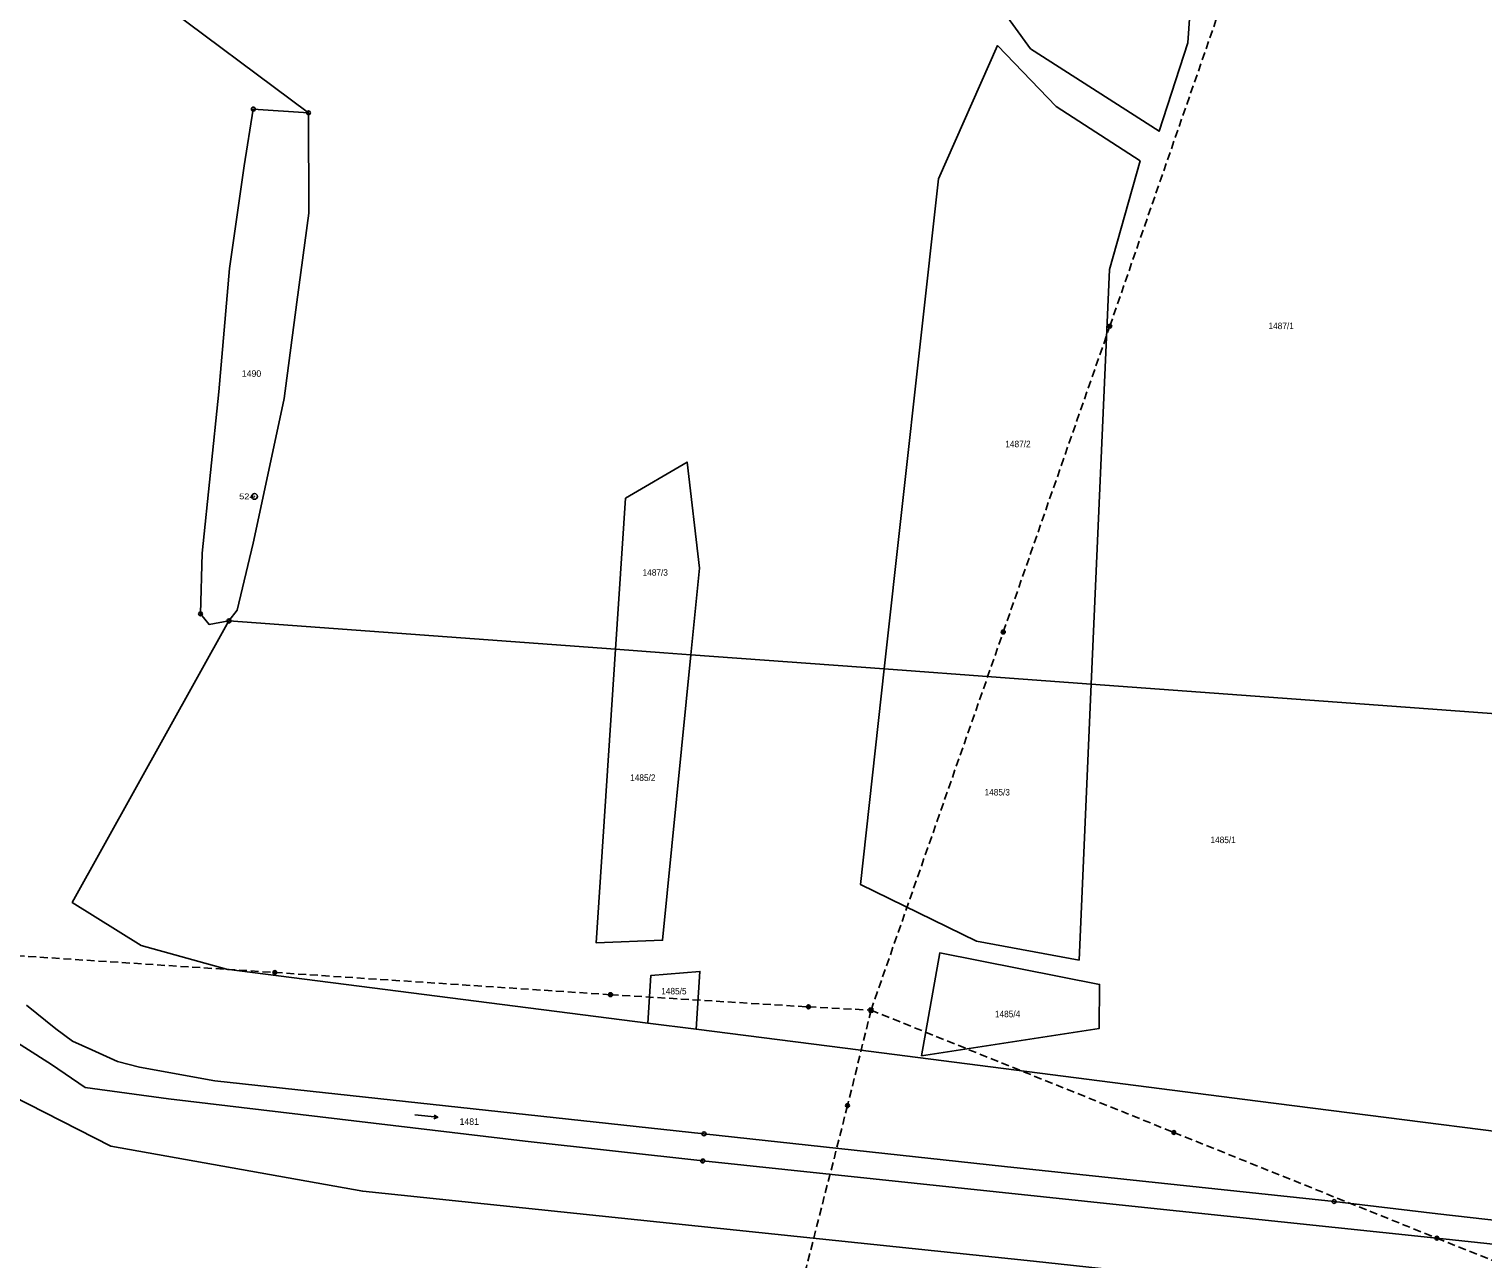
# Model space of a CAD drawing. Extents: x -872229 to -869198, y -1075981 to -1074329.
# Drawn here: x -871585.9 to -871207, y -1075209.5 to -1074889 of the extents above; entities that cross this region are included whole.
import ezdxf
from ezdxf.enums import TextEntityAlignment as Align

# ---------------------------------------------------------------- set-up
doc = ezdxf.new("R2010")
doc.units = 0
doc.header["$LTSCALE"] = 0.68
doc.linetypes.add('MEDIUM_DASHED', pattern=[4.5, 3, -1.5])
for name, color, linetype, lineweight in [('1', 7, 'Continuous', 25), ('3', 7, 'Continuous', 25), ('6', 7, 'Continuous', 25), ('8', 7, 'Continuous', 25)]:
    doc.layers.add(name, color=color, linetype=linetype, lineweight=lineweight)
doc.layers.add('2', color=7, linetype='Continuous')

msp = doc.modelspace()

# ---------------------------------------------------------------- linework, layer by layer
at = {"layer": '1'}
msp.add_line((-871513.08, -1074910.82), (-871584.85, -1074857.22), dxfattribs=at)
for points in [[(-871282.11, -1074866.22), (-871283.92, -1074892.6), (-871291.38, -1074915.63), (-871324.89, -1074894.16), (-871340.13, -1074873.1), (-871340.87, -1074864.14)], [(-871363.02, -1075055.76), (-871348.93, -1074928.05), (-871333.5, -1074893.3), (-871318.24, -1074909.17), (-871296.36, -1074923.36), (-871304.36, -1074951.64), (-871309.09, -1075059.71)], [(-871513.08, -1074910.82), (-871527.47, -1074909.84), (-871529.87, -1074924.66), (-871533.68, -1074951.43), (-871536.46, -1074983.57), (-871540.84, -1075025.59), (-871541.23, -1075041.38), (-871539.02, -1075044.15), (-871533.81, -1075043.24)], [(-871533.81, -1075043.24), (-871531.71, -1075040.41), (-871527.51, -1075022.97), (-871522.91, -1075001.53), (-871519.39, -1074985.24), (-871516.11, -1074960.17), (-871512.99, -1074936.96), (-871513.08, -1074910.82)], [(-871433.09, -1075050.62), (-871430.49, -1075011.26), (-871414.41, -1075001.84), (-871411.15, -1075029.47), (-871413.4, -1075052.07)], [(-871424.63, -1075148.05), (-871534.47, -1075134.02), (-871556.74, -1075127.83), (-871574.66, -1075116.59), (-871533.81, -1075043.24)], [(-871413.4, -1075052.07), (-871420.8, -1075126.47), (-871438.15, -1075127.13), (-871433.09, -1075050.62), (-871533.81, -1075043.24)], [(-871413.4, -1075052.07), (-871420.47, -1075051.55), (-871433.09, -1075050.62)], [(-871309.09, -1075059.71), (-871312.23, -1075131.62), (-871339.02, -1075126.74), (-871369.22, -1075111.94), (-871363.02, -1075055.76), (-871413.4, -1075052.07)], [(-871309.09, -1075059.71), (-871332.7, -1075057.98), (-871363.02, -1075055.76)], [(-871124.45, -1075073.24), (-871227.17, -1075065.71), (-871309.09, -1075059.71)], [(-871424.63, -1075148.05), (-871423.87, -1075135.7), (-871411.08, -1075134.58), (-871412.02, -1075149.67)], [(-871185.02, -1075201.57), (-871218.75, -1075197.81), (-871245.79, -1075194.55), (-871331.72, -1075185.46), (-871410.01, -1075176.94), (-871537.47, -1075163.08), (-871557.12, -1075159.53), (-871562.9, -1075158.08), (-871569.58, -1075155.03), (-871574.62, -1075152.74), (-871578.94, -1075149.53), (-871586.61, -1075143.41)], [(-871595.04, -1075149.42), (-871580.06, -1075158.85), (-871571.27, -1075164.84), (-871549.56, -1075167.77), (-871456.66, -1075178.8), (-871410.34, -1075183.99), (-871300.12, -1075195.6), (-871219.01, -1075204.11), (-871182.37, -1075208)], [(-871164.62, -1075181.27), (-871265.65, -1075168.37), (-871373.25, -1075154.62), (-871412.02, -1075149.67), (-871424.63, -1075148.05)], [(-871152.53, -1075228.75), (-871324.15, -1075210.15), (-871498.95, -1075191.88), (-871564.6, -1075180.17), (-871590.36, -1075167.06), (-871608.79, -1075266.42)]]:
    msp.add_lwpolyline(points, dxfattribs=at)
msp.add_lwpolyline([(-871353.31, -1075156.61), (-871348.55, -1075129.76), (-871306.92, -1075137.97), (-871307.02, -1075149.48)], close=True, dxfattribs=at)
at = {"layer": '3'}
msp.add_line((-871479.39, -1075172.624), (-871480.414, -1075173.02), dxfattribs=at)
msp.add_lwpolyline([(-871485.357, -1075171.997), (-871479.39, -1075172.624), (-871480.31, -1075172.023)], dxfattribs=at)
at = {"layer": '6', "linetype": 'MEDIUM_DASHED'}
for p, q in [((-871366.48, -1075144.68), (-871332.01, -1075046.13)), ((-871382.8, -1075143.84), (-871366.48, -1075144.68)), ((-871366.48, -1075144.68), (-871372.59, -1075169.57)), ((-871366.48, -1075144.68), (-871287.54, -1075176.57)), ((-871287.54, -1075176.57), (-871219.01, -1075204.11)), ((-871219.01, -1075204.11), (-871164.94, -1075225.78))]:
    msp.add_line(p, q, dxfattribs=at)
at = {"layer": '6'}
for p, q in [((-871366.982, -1075144.179), (-871365.981, -1075144.179)), ((-871366.982, -1075145.179), (-871366.982, -1075144.179)), ((-871366.982, -1075144.379), (-871365.981, -1075144.379)), ((-871366.982, -1075144.579), (-871365.981, -1075144.579)), ((-871366.982, -1075144.779), (-871365.981, -1075144.779)), ((-871366.982, -1075144.979), (-871365.981, -1075144.979)), ((-871366.982, -1075145.179), (-871365.981, -1075145.179)), ((-871366.781, -1075145.179), (-871366.781, -1075144.179)), ((-871366.582, -1075145.179), (-871366.582, -1075144.179)), ((-871366.381, -1075145.179), (-871366.381, -1075144.179)), ((-871366.182, -1075145.179), (-871366.182, -1075144.179)), ((-871365.981, -1075145.179), (-871365.981, -1075144.179))]:
    msp.add_line(p, q, dxfattribs=at)
at = {"layer": '6', "linetype": 'MEDIUM_DASHED'}
for points in [[(-871332.01, -1075046.13), (-871304.24, -1074966.42), (-871273.46, -1074877.72)], [(-871694.96, -1075123.52), (-871610.56, -1075129.11), (-871521.87, -1075134.87)], [(-871521.87, -1075134.87), (-871434.35, -1075140.66), (-871382.8, -1075143.84)], [(-871372.59, -1075169.57), (-871383.31, -1075211.56), (-871405.77, -1075298.4)]]:
    msp.add_lwpolyline(points, dxfattribs=at)
at = {"layer": '6'}
for centre, radius in [((-871304.2434, -1074966.4199), 0.5), ((-871304.2434, -1074966.4199), 0.4), ((-871304.2434, -1074966.4199), 0.3), ((-871304.2434, -1074966.4199), 0.2), ((-871304.2434, -1074966.4199), 0.1), ((-871332.0134, -1075046.1299), 0.5), ((-871332.0134, -1075046.1299), 0.4), ((-871332.0134, -1075046.1299), 0.3), ((-871332.0134, -1075046.1299), 0.2), ((-871332.0134, -1075046.1299), 0.1), ((-871521.8734, -1075134.8699), 0.5), ((-871521.8734, -1075134.8699), 0.4), ((-871521.8734, -1075134.8699), 0.3), ((-871521.8734, -1075134.8699), 0.2), ((-871521.8734, -1075134.8699), 0.1), ((-871434.3534, -1075140.6599), 0.5), ((-871434.3534, -1075140.6599), 0.4), ((-871434.3534, -1075140.6599), 0.3), ((-871434.3534, -1075140.6599), 0.2), ((-871434.3534, -1075140.6599), 0.1), ((-871382.8034, -1075143.8399), 0.5), ((-871382.8034, -1075143.8399), 0.4), ((-871382.8034, -1075143.8399), 0.3), ((-871382.8034, -1075143.8399), 0.2), ((-871382.8034, -1075143.8399), 0.1), ((-871372.5934, -1075169.5699), 0.5), ((-871372.5934, -1075169.5699), 0.4), ((-871372.5934, -1075169.5699), 0.3), ((-871372.5934, -1075169.5699), 0.2), ((-871372.5934, -1075169.5699), 0.1), ((-871287.5434, -1075176.5699), 0.5), ((-871287.5434, -1075176.5699), 0.4), ((-871287.5434, -1075176.5699), 0.3), ((-871287.5434, -1075176.5699), 0.2), ((-871287.5434, -1075176.5699), 0.1), ((-871219.0134, -1075204.1099), 0.5), ((-871219.0134, -1075204.1099), 0.4), ((-871219.0134, -1075204.1099), 0.3), ((-871219.0134, -1075204.1099), 0.2), ((-871219.0134, -1075204.1099), 0.1)]:
    msp.add_circle(centre, radius, dxfattribs=at)
at = {"layer": '8'}
for centre, radius in [((-871527.47, -1074909.8399), 0.5), ((-871527.47, -1074909.8399), 0.0303), ((-871513.08, -1074910.8199), 0.5), ((-871513.08, -1074910.8199), 0.0303), ((-871527.15, -1075010.7898), 0.75), ((-871527.15, -1075010.7898), 0.03), ((-871541.23, -1075041.3799), 0.5), ((-871541.23, -1075041.3799), 0.0303), ((-871533.81, -1075043.2399), 0.5), ((-871533.81, -1075043.2399), 0.0303), ((-871410.01, -1075176.9399), 0.5), ((-871410.01, -1075176.9399), 0.0303), ((-871410.34, -1075183.9899), 0.5), ((-871410.34, -1075183.9899), 0.0303), ((-871245.79, -1075194.5499), 0.5), ((-871245.79, -1075194.5499), 0.0303)]:
    msp.add_circle(centre, radius, dxfattribs=at)

# ---------------------------------------------------------------- texts
at = {"layer": '2', "width": 0.95}
for s, p in [('1487/1', (-871262.88, -1074967.19)), ('1487/2', (-871331.48, -1074997.98)), ('1487/3', (-871426.02, -1075031.47)), ('1485/2', (-871429.26, -1075084.95)), ('1485/3', (-871336.89, -1075088.74)), ('1485/1', (-871278.01, -1075101.16)), ('1485/5', (-871421.16, -1075140.59)), ('1485/4', (-871334.19, -1075146.54))]:
    msp.add_text(s, height=1.7, dxfattribs=at).set_placement(p)
at = {"layer": '2'}
for s, p in [('1490', (-871530.47, -1074979.62)), ('1481', (-871473.72, -1075174.59))]:
    msp.add_text(s, height=1.7, dxfattribs=at).set_placement(p)
at = {"layer": '8', "width": 1.2}
msp.add_text('524', height=1.5, dxfattribs=at).set_placement((-871527.15, -1075011.54), align=Align.RIGHT)

doc.saveas('drawing.dxf')
